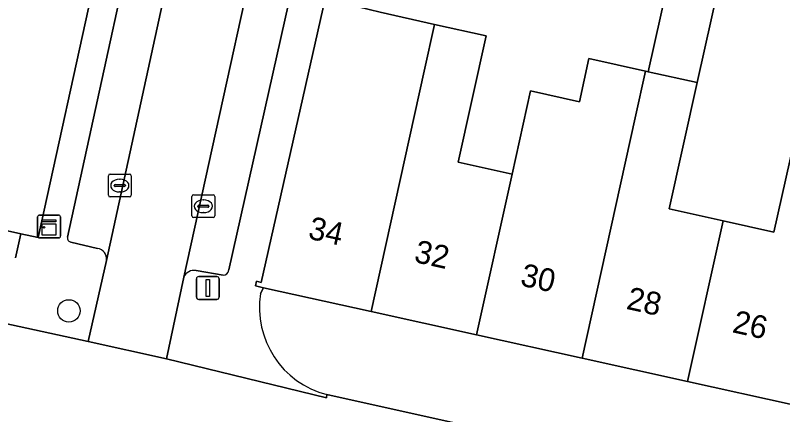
# Model space of a CAD drawing. Extents: x 162172 to 163187, y 382874 to 383685.
# Drawn here: x 163018.49 to 163052.14, y 383102.88 to 383120.38 of the extents above; entities that cross this region are included whole.
import ezdxf

# ---------------------------------------------------------------- set-up
doc = ezdxf.new("R2010")
doc.units = 0
for name, color, linetype in [('IMGEO_Boom', 7, 'Continuous'), ('IMGEO_Erf', 7, 'Continuous'), ('IMGEO_Kast', 7, 'Continuous'), ('IMGEO_Kolk', 7, 'Continuous'), ('IMGEO_Lichtmast', 7, 'Continuous'), ('IMGEO_Pand', 7, 'Continuous'), ('IMGEO_Pand_nummerreeks', 7, 'Continuous'), ('IMGEO_Parkeervlak_open', 7, 'Continuous'), ('IMGEO_Rijbaan_lokaal_open', 7, 'Continuous'), ('IMGEO_Voetpad_open', 7, 'Continuous')]:
    doc.layers.add(name, color=color, linetype=linetype)

msp = doc.modelspace()

# ---------------------------------------------------------------- linework, layer by layer
at = {"layer": 'IMGEO_Boom'}
msp.add_circle((163020.84, 383107.43), 0.489, dxfattribs=at)
at = {"layer": 'IMGEO_Erf'}
for points in [[(163047.622, 383124.122), (163044.042, 383124.672), (163044.637, 383127.317), (163044.981, 383129.981), (163042.797, 383130.377), (163042.384, 383127.642), (163038.812, 383128.181), (163038.11, 383125.06), (163033.233, 383126.158), (163032.072, 383121.12), (163034.487, 383120.513), (163036.871, 383119.984), (163039.136, 383119.482), (163037.909, 383113.95), (163040.271, 383113.426), (163041.077, 383117.068), (163043.222, 383116.593), (163043.641, 383118.483), (163046.121, 383117.933), (163046.242, 383117.906)], [(163056.356, 383120.39), (163056.667, 383122.937), (163057.043, 383122.891), (163057.448, 383125.312), (163053.935, 383125.826), (163054.391, 383128.555), (163051.953, 383128.911), (163051.599, 383126.167), (163050.37, 383126.356), (163049.947, 383124.452), (163048.389, 383117.431), (163047.161, 383111.899), (163049.522, 383111.376), (163051.755, 383110.881), (163052.984, 383116.412), (163053.364, 383118.123), (163055.75, 383117.593)]]:
    msp.add_lwpolyline(points, close=True, dxfattribs=at)
for points in [[(163018.493, 383109.759), (163018.734, 383110.811), (163013.791, 383111.904)], [(163080.285, 383096.581), (163080.543, 383097.511), (163076.075, 383098.433), (163076.021, 383098.162), (163075.818, 383098.201), (163075.537, 383098.256), (163071.096, 383099.236), (163066.47, 383100.257), (163061.845, 383101.278), (163057.218, 383102.3), (163052.592, 383103.321), (163047.965, 383104.342), (163043.34, 383105.363), (163038.713, 383106.384), (163034.087, 383107.405), (163029.377, 383108.445), (163029.245, 383108.188)], [(163032.156, 383103.761), (163074.821, 383094.284)]]:
    msp.add_lwpolyline(points, dxfattribs=at)
msp.add_arc((163033.129, 383107.572), 3.933, 170.9822, 255.6721, dxfattribs=at)
at = {"layer": 'IMGEO_Kast'}
for p, q in [((163019.471, 383110.703), (163019.471, 383111.544)), ((163019.471, 383111.544), (163019.471, 383110.703)), ((163019.546, 383111.628), (163020.387, 383111.628)), ((163020.387, 383111.628), (163019.546, 383111.628)), ((163020.471, 383111.553), (163020.471, 383110.712)), ((163020.471, 383110.712), (163020.471, 383111.553)), ((163020.396, 383110.628), (163019.555, 383110.628)), ((163019.555, 383110.628), (163020.396, 383110.628))]:
    msp.add_line(p, q, dxfattribs=at)
for points in [[(163019.666, 383111.418), (163020.266, 383111.418), (163020.266, 383111.333), (163019.666, 383111.333), (163019.666, 383111.418)], [(163019.666, 383111.243), (163020.266, 383111.243), (163020.266, 383110.754), (163019.666, 383110.754), (163019.666, 383111.243)]]:
    msp.add_lwpolyline(points, dxfattribs=at)
msp.add_circle((163019.75, 383111.092), 0.0377, dxfattribs=at)
for centre, start, end in [((163019.549, 383111.55), 92.4484, 184.2845), ((163019.549, 383111.55), 92.4484, 184.2845), ((163020.393, 383111.55), 2.4484, 94.2845), ((163020.393, 383111.55), 2.4484, 94.2845), ((163019.549, 383110.706), 182.4484, 274.2845), ((163019.549, 383110.706), 182.4484, 274.2845), ((163020.393, 383110.706), 272.4484, 4.2845), ((163020.393, 383110.706), 272.4484, 4.2845)]:
    msp.add_arc(centre, 0.0779, start, end, dxfattribs=at)
at = {"layer": 'IMGEO_Kolk'}
for p, q in [((163022.648, 383113.421), (163023.5, 383113.421)), ((163022.573, 383112.495), (163022.573, 383113.347)), ((163023.061, 383113.201), (163023.086, 383113.201)), ((163023.574, 383113.347), (163023.574, 383112.495)), ((163022.832, 383112.915), (163022.832, 383112.927)), ((163023.27, 383112.878), (163022.872, 383112.878)), ((163022.875, 383112.964), (163023.273, 383112.964)), ((163023.316, 383112.927), (163023.316, 383112.915)), ((163023.5, 383112.421), (163022.648, 383112.421)), ((163023.084, 383112.641), (163023.059, 383112.641)), ((163026.236, 383111.589), (163026.236, 383112.441)), ((163026.311, 383112.515), (163027.163, 383112.515)), ((163027.237, 383112.441), (163027.237, 383111.589)), ((163026.724, 383112.295), (163026.749, 383112.295)), ((163026.495, 383112.009), (163026.495, 383112.021)), ((163026.933, 383111.972), (163026.535, 383111.972)), ((163026.538, 383112.058), (163026.936, 383112.058)), ((163026.747, 383111.735), (163026.722, 383111.735)), ((163026.979, 383112.021), (163026.979, 383112.009)), ((163027.163, 383111.515), (163026.311, 383111.515))]:
    msp.add_line(p, q, dxfattribs=at)
for points in [[(163022.648, 383113.421), (163023.5, 383113.421)], [(163022.573, 383112.495), (163022.573, 383113.347)], [(163023.574, 383113.347), (163023.574, 383112.495)], [(163023.5, 383112.421), (163022.648, 383112.421)], [(163026.236, 383111.589), (163026.236, 383112.441)], [(163026.311, 383112.515), (163027.163, 383112.515)], [(163027.237, 383112.441), (163027.237, 383111.589)], [(163027.163, 383111.515), (163026.311, 383111.515)]]:
    msp.add_lwpolyline(points, dxfattribs=at)
for centre, radius, start, end in [((163022.65, 383113.345), 0.0765, 91.552, 178.448), ((163022.65, 383113.345), 0.0765, 91.552, 178.448), ((163023.498, 383113.345), 0.0765, 1.552, 88.448), ((163023.498, 383113.345), 0.0765, 1.552, 88.448), ((163022.872, 383112.924), 0.0403, 85.8775, 175.7526), ((163022.869, 383112.914), 0.0366, 178.938, 274.7102), ((163023.273, 383112.921), 0.043, 264.8664, 352.4533), ((163023.277, 383112.926), 0.0386, 1.7309, 96.639), ((163022.65, 383112.497), 0.0765, 181.552, 268.448), ((163022.65, 383112.497), 0.0765, 181.552, 268.448), ((163023.498, 383112.497), 0.0765, 271.552, 358.448), ((163023.498, 383112.497), 0.0765, 271.552, 358.448), ((163026.313, 383112.439), 0.0765, 91.552, 178.448), ((163026.313, 383112.439), 0.0765, 91.552, 178.448), ((163027.161, 383112.439), 0.0765, 1.552, 88.448), ((163027.161, 383112.439), 0.0765, 1.552, 88.448), ((163026.535, 383112.018), 0.0403, 85.8775, 175.7526), ((163026.532, 383112.008), 0.0366, 178.938, 274.7102), ((163026.936, 383112.015), 0.043, 264.8664, 352.4533), ((163026.94, 383112.02), 0.0386, 1.7309, 96.639), ((163026.313, 383111.591), 0.0765, 181.552, 268.448), ((163026.313, 383111.591), 0.0765, 181.552, 268.448), ((163027.161, 383111.591), 0.0765, 271.552, 358.448), ((163027.161, 383111.591), 0.0765, 271.552, 358.448)]:
    msp.add_arc(centre, radius, start, end, dxfattribs=at)
for centre, major_axis, ratio, start_param, end_param in [((163023.06, 383112.921), (-0.387, 0.002), 0.722429, 4.712389, 7.853982), ((163023.085, 383112.921), (-0.39, 0.002), 0.717154, 1.570796, 4.712389), ((163026.723, 383112.015), (-0.387, 0.002), 0.722429, 4.712389, 7.853982), ((163026.748, 383112.015), (-0.39, 0.002), 0.717154, 1.570796, 4.712389)]:
    msp.add_ellipse(centre, major_axis=major_axis, ratio=ratio, start_param=start_param, end_param=end_param, dxfattribs=at)
at = {"layer": 'IMGEO_Lichtmast'}
for p, q in [((163026.434, 383108.036), (163026.434, 383108.836)), ((163026.434, 383108.836), (163026.434, 383108.036)), ((163026.534, 383108.936), (163027.324, 383108.936)), ((163027.324, 383108.936), (163026.534, 383108.936)), ((163027.424, 383108.836), (163027.424, 383108.036)), ((163027.424, 383108.036), (163027.424, 383108.836)), ((163027.324, 383107.936), (163026.534, 383107.936)), ((163026.534, 383107.936), (163027.324, 383107.936))]:
    msp.add_line(p, q, dxfattribs=at)
msp.add_lwpolyline([(163026.854, 383108.811), (163027.004, 383108.811), (163027.004, 383108.061), (163026.854, 383108.061), (163026.854, 383108.811)], dxfattribs=at)
for centre, start, end in [((163026.534, 383108.836), 90, 180), ((163026.534, 383108.836), 90, 180), ((163027.324, 383108.836), 0, 90), ((163027.324, 383108.836), 360, 90), ((163026.534, 383108.036), 180, 270), ((163026.534, 383108.036), 180, 270), ((163027.324, 383108.036), 270, 0), ((163027.324, 383108.036), 270, 0)]:
    msp.add_arc(centre, 0.1, start, end, dxfattribs=at)
at = {"layer": 'IMGEO_Pand'}
for points in [[(163049.947, 383124.452), (163050.37, 383126.356), (163048.197, 383126.69), (163047.788, 383124.865), (163047.622, 383124.122), (163046.242, 383117.906), (163048.389, 383117.431)], [(163021.966, 383121.901), (163019.425, 383122.469), (163016.924, 383123.028), (163016.681, 383121.931), (163016.039, 383122.074), (163015.403, 383119.196), (163013.791, 383111.904), (163018.734, 383110.811), (163019.497, 383110.642)], [(163036.871, 383119.984), (163034.487, 383120.513), (163032.072, 383121.12), (163029.271, 383108.675), (163029.069, 383108.732), (163029.019, 383108.524), (163029.377, 383108.445), (163034.087, 383107.405), (163036.418, 383117.937)], [(163038.713, 383106.384), (163040.271, 383113.426), (163037.909, 383113.95), (163039.136, 383119.482), (163036.871, 383119.984), (163036.418, 383117.937), (163034.087, 383107.405)], [(163038.713, 383106.384), (163043.34, 383105.363), (163045.669, 383115.89), (163046.121, 383117.933), (163043.641, 383118.483), (163043.222, 383116.593), (163041.077, 383117.068), (163040.271, 383113.426)], [(163049.522, 383111.376), (163047.161, 383111.899), (163048.389, 383117.431), (163046.242, 383117.906), (163046.121, 383117.933), (163045.669, 383115.89), (163043.34, 383105.363), (163047.965, 383104.342)], [(163047.965, 383104.342), (163052.592, 383103.321), (163054.919, 383113.835), (163055.75, 383117.593), (163053.364, 383118.123), (163052.984, 383116.412), (163051.755, 383110.881), (163049.522, 383111.376)]]:
    msp.add_lwpolyline(points, close=True, dxfattribs=at)
at = {"layer": 'IMGEO_Parkeervlak_open'}
for points in [[(163022.495, 383109.64), (163026.76, 383129.231), (163026.869, 383129.807), (163026.979, 383130.383), (163027.448, 383132.692), (163031.942, 383162.715), (163034.322, 383178.584), (163034.707, 383181.151), (163034.878, 383182.293), (163041.863, 383228.565)], [(163030.638, 383130.526), (163030.43, 383129.579), (163025.877, 383108.905)], [(163024.831, 383129.199), (163020.785, 383110.656)], [(163027.854, 383109.222), (163030.658, 383121.75), (163031.935, 383127.642)], [(163020.928, 383110.438), (163022.089, 383110.168)], [(163026.417, 383109.195), (163027.6, 383108.997)]]:
    msp.add_lwpolyline(points, dxfattribs=at)
for centre, radius, start, end in [((163020.958, 383110.614), 0.178, 166.3338, 260.193), ((163022.013, 383109.689), 0.485, 354.1434, 80.9728), ((163026.32, 383108.728), 0.477, 78.2758, 158.1991), ((163027.609, 383109.243), 0.246, 267.9127, 355.1581)]:
    msp.add_arc(centre, radius, start, end, dxfattribs=at)
at = {"layer": 'IMGEO_Rijbaan_lokaal_open'}
msp.add_lwpolyline([(163030.43, 383129.579), (163026.979, 383130.383), (163026.869, 383129.807), (163026.76, 383129.231), (163022.495, 383109.64), (163021.691, 383106.09), (163025.113, 383105.327), (163025.877, 383108.905)], close=True, dxfattribs=at)
at = {"layer": 'IMGEO_Voetpad_open'}
for points in [[(163043.453, 383259.501), (163043.302, 383258.58), (163042.291, 383251.846), (163041.773, 383248.496), (163041.692, 383247.97), (163039.68, 383234.953), (163039.263, 383232.162), (163039.037, 383230.674), (163024.437, 383134.63), (163024.221, 383133.207), (163023.786, 383130.253), (163021.966, 383121.901), (163019.497, 383110.642), (163018.734, 383110.811), (163018.493, 383109.759)], [(163029.245, 383108.188), (163029.377, 383108.445), (163029.019, 383108.524), (163029.069, 383108.732), (163029.271, 383108.675), (163032.072, 383121.12), (163033.233, 383126.158), (163033.847, 383128.823), (163034.275, 383131.629), (163034.476, 383133.047), (163034.477, 383133.054), (163037.149, 383151.861), (163051.971, 383250)], [(163025.113, 383105.327), (163021.691, 383106.09), (163014.15, 383107.727), (163000, 383110.85), (162970.558, 383117.347), (162963.175, 383118.833), (162959.964, 383119.516), (162952.155, 383121.467), (162908.878, 383131), (162908.832, 383130.883), (162900.887, 383132.611), (162897.714, 383133.338), (162893.836, 383129.896), (162897.009, 383129.178), (162902.768, 383127.876), (162902.668, 383127.387), (162904.361, 383127.004), (162907.758, 383126.235), (162908.106, 383126.159)], [(163020.785, 383110.656), (163024.831, 383129.199)], [(163031.935, 383127.642), (163030.658, 383121.75), (163027.854, 383109.222)], [(163022.089, 383110.168), (163020.928, 383110.438)], [(163016.933, 383108.071), (163015.557, 383107.772), (163014.15, 383107.727), (163021.691, 383106.09), (163022.495, 383109.64)], [(163027.6, 383108.997), (163026.417, 383109.195)], [(163025.877, 383108.905), (163025.113, 383105.327), (163032.135, 383103.625), (163032.156, 383103.761)], [(163074.821, 383094.284), (163032.156, 383103.761), (163032.135, 383103.625), (163025.113, 383105.327)]]:
    msp.add_lwpolyline(points, dxfattribs=at)
for centre, radius, start, end in [((163020.958, 383110.614), 0.178, 166.3338, 260.193), ((163022.013, 383109.689), 0.485, 354.1434, 80.9728), ((163026.32, 383108.728), 0.477, 78.2758, 158.1991), ((163027.609, 383109.243), 0.246, 267.9127, 355.1581), ((163033.129, 383107.572), 3.933, 170.9822, 255.6721)]:
    msp.add_arc(centre, radius, start, end, dxfattribs=at)

# ---------------------------------------------------------------- texts
at = {"layer": 'IMGEO_Pand_nummerreeks'}
for s, rotation, p in [('34', 347.5526, (163031.288, 383110.604)), ('32', 347.5526, (163035.934, 383109.579)), ('30', 347.5526, (163040.59, 383108.55)), ('28', 347.5554, (163045.24, 383107.524)), ('26', 347.5526, (163049.886, 383106.499))]:
    msp.add_text(s, height=1, rotation=rotation, dxfattribs=at).set_placement(p)

doc.saveas('drawing.dxf')
